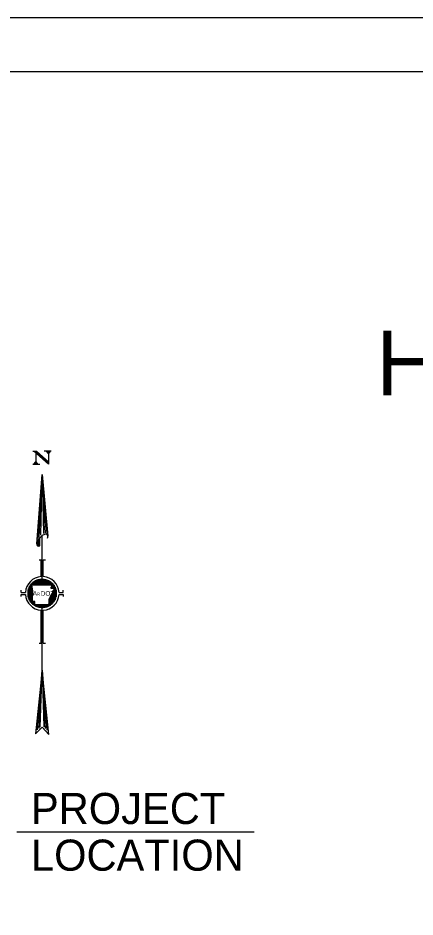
# Model space of a CAD drawing. Extents: x -0.3 to 2.65, y 0 to 1.9.
# Drawn here: x 0.3593 to 0.5124, y 0.5699 to 0.9167 of the extents above; entities that cross this region are included whole.
import ezdxf

# ---------------------------------------------------------------- set-up
doc = ezdxf.new("R2010")
doc.units = 0
for name, color, linetype in [('Default', 7, 'Continuous'), ('SHET_Annotations', 7, 'Continuous'), ('SHET_Border-Lines', 7, 'Continuous'), ('SHET_Border-Text', 7, 'Continuous')]:
    doc.layers.add(name, color=color, linetype=linetype)

msp = doc.modelspace()

# ---------------------------------------------------------------- linework, layer by layer
at = {"layer": 'Default'}
msp.add_line((0.3588331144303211, 0.6027512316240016), (0.4503996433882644, 0.6027512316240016), dxfattribs=at)
at = {"layer": 'SHET_Border-Lines'}
for points in [[(0, 0), (1.416666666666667, 0), (1.416666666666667, 0.9166666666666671), (0, 0.9166666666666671)], [(0.02083333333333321, 0.02083333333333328), (1.3958333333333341, 0.02083333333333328), (1.3958333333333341, 0.8958333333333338), (0.02083333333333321, 0.8958333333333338)]]:
    msp.add_lwpolyline(points, close=True, dxfattribs=at)
at = {"layer": 'SHET_Border-Text'}
for p, q in [((0.36499485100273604, 0.7495318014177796), (0.36647240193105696, 0.7495318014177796)), ((0.3654447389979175, 0.7495318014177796), (0.37101124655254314, 0.7445858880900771)), ((0.3655086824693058, 0.7495318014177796), (0.37101124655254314, 0.7446504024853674)), ((0.365573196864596, 0.7495318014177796), (0.37101124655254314, 0.7446932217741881)), ((0.3656371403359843, 0.7495318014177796), (0.37101124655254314, 0.7447571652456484)), ((0.36570165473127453, 0.7495318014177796), (0.37101124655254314, 0.7447999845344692)), ((0.3657655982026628, 0.7495318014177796), (0.37101124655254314, 0.7448644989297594)), ((0.3658084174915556, 0.7495318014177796), (0.37101124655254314, 0.7449073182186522)), ((0.36587293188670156, 0.7495318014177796), (0.37101124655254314, 0.7449712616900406)), ((0.3659368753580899, 0.7495318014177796), (0.37101124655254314, 0.7450140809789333)), ((0.36600138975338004, 0.7495318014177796), (0.37101124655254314, 0.7450785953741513)), ((0.36606533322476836, 0.7495318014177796), (0.37101124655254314, 0.7451425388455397)), ((0.36612984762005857, 0.7495318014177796), (0.37101124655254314, 0.7451853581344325)), ((0.366150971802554, 0.7495318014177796), (0.366150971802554, 0.7445858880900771)), ((0.36619379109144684, 0.7495318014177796), (0.37101124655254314, 0.7452498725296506)), ((0.3662366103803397, 0.7495318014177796), (0.37101124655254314, 0.7452926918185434)), ((0.3663011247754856, 0.7495318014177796), (0.37101124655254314, 0.7453566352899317)), ((0.3663650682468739, 0.7495318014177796), (0.37101124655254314, 0.7453994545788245)), ((0.36642958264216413, 0.7495318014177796), (0.37101124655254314, 0.7454639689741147)), ((0.36647240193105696, 0.7495318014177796), (0.37101124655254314, 0.7454850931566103)), ((0.3706898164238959, 0.7495318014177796), (0.3694480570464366, 0.7495318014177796)), ((0.3721456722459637, 0.7495318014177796), (0.3706898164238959, 0.7495318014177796)), ((0.37101124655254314, 0.7495318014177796), (0.37101124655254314, 0.7445858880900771)), ((0.36499485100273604, 0.7445858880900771), (0.36647240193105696, 0.7445858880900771)), ((0.36647240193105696, 0.7445858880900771), (0.36771416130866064, 0.7445858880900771)), ((0.3669862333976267, 0.713070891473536), (0.3669862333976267, 0.7146123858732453)), ((0.36728596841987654, 0.7130069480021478), (0.36728596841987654, 0.7150622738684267)), ((0.36767134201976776, 0.7130069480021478), (0.36767134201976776, 0.716025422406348)), ((0.36865618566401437, 0.7003752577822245), (0.36865618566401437, 0.7169891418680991)), ((0.36666480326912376, 0.7133278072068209), (0.36666480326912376, 0.7139700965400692)), ((0.3674355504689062, 0.7076328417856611), (0.3682491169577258, 0.7076328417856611)), ((0.3682491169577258, 0.7011671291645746), (0.3682491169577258, 0.7076328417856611)), ((0.36906268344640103, 0.701188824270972), (0.36906268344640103, 0.7076328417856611)), ((0.36906268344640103, 0.7076328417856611), (0.3698762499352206, 0.7076328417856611)), ((0.3635818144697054, 0.6922607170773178), (0.3635818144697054, 0.6971209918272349)), ((0.36377478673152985, 0.6919181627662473), (0.36377478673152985, 0.6974846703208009)), ((0.363988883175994, 0.6915973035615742), (0.363988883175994, 0.6978061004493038)), ((0.3641812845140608, 0.6912975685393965), (0.3641812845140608, 0.6981269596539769)), ((0.36439538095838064, 0.6911045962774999), (0.36439538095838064, 0.6983838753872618)), ((0.3645883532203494, 0.6908693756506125), (0.3645883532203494, 0.6985768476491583)), ((0.3650376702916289, 0.6955366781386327), (0.3646522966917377, 0.6980201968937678)), ((0.3646522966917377, 0.6980201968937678), (0.372060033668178, 0.6980201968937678)), ((0.3648024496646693, 0.6980201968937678), (0.3648024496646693, 0.6987909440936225)), ((0.36499485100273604, 0.6980201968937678), (0.36499485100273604, 0.6989622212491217)), ((0.3652089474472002, 0.6980201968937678), (0.3652089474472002, 0.6991546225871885)), ((0.3654019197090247, 0.6980201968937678), (0.3654019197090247, 0.6993047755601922)), ((0.3656160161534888, 0.6980201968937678), (0.3656160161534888, 0.6994332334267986)), ((0.3658084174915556, 0.6980201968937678), (0.3658084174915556, 0.6995616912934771)), ((0.36602251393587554, 0.6980201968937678), (0.36602251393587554, 0.6996684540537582)), ((0.3662154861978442, 0.6980201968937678), (0.3662154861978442, 0.6997757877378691)), ((0.36642958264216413, 0.6980201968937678), (0.36642958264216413, 0.6998614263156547)), ((0.36662198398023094, 0.6980201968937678), (0.36662198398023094, 0.6999470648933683)), ((0.36681495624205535, 0.6980201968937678), (0.36681495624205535, 0.700032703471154)), ((0.36702905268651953, 0.6980201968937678), (0.36702905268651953, 0.7000966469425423)), ((0.36722145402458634, 0.6980201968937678), (0.36722145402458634, 0.7001611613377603)), ((0.3674355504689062, 0.6980201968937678), (0.3674355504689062, 0.7002039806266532)), ((0.36762852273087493, 0.6980201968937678), (0.36762852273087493, 0.700246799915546)), ((0.3678426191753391, 0.6980201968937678), (0.3678426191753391, 0.7002679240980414)), ((0.3680350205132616, 0.6980201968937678), (0.3680350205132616, 0.7003107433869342)), ((0.3682491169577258, 0.6980201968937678), (0.3682491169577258, 0.7003324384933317)), ((0.3684420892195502, 0.6980201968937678), (0.3684420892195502, 0.7003535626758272)), ((0.36865618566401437, 0.6980201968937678), (0.36865618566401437, 0.7003752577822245)), ((0.3688485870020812, 0.6980201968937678), (0.3688485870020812, 0.7003324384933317)), ((0.36906268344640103, 0.6980201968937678), (0.36906268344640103, 0.7003324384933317)), ((0.36925565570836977, 0.6980201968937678), (0.36925565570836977, 0.7002896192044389)), ((0.3694697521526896, 0.6980201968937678), (0.3694697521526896, 0.7002679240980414)), ((0.36966215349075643, 0.6980201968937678), (0.36966215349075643, 0.7002251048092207)), ((0.3698762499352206, 0.6980201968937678), (0.3698762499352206, 0.7001822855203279)), ((0.370069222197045, 0.6980201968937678), (0.370069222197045, 0.7001394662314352)), ((0.37026162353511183, 0.6980201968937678), (0.37026162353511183, 0.7000755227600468)), ((0.370475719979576, 0.6980201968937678), (0.370475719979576, 0.7000110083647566)), ((0.3706686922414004, 0.6980201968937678), (0.3706686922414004, 0.6999470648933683)), ((0.3708827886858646, 0.6980201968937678), (0.3708827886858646, 0.6998614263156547)), ((0.3710751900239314, 0.6980201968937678), (0.3710751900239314, 0.6997757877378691)), ((0.3712892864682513, 0.6980201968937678), (0.3712892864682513, 0.6996684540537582)), ((0.37148225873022, 0.6980201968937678), (0.37148225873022, 0.6995616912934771)), ((0.3716963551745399, 0.6980201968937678), (0.3716963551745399, 0.6994332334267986)), ((0.3718887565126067, 0.6980201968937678), (0.3718887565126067, 0.6992830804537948)), ((0.37218849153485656, 0.6973562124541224), (0.3719104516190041, 0.6967784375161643)), ((0.372060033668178, 0.6980201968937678), (0.372060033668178, 0.6980201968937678)), ((0.372060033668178, 0.6980201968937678), (0.37223131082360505, 0.6977204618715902)), ((0.37210285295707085, 0.6979773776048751), (0.37210285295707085, 0.6991546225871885)), ((0.37210285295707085, 0.6967784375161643), (0.37210285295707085, 0.6971421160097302)), ((0.37223131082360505, 0.6977204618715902), (0.37218849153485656, 0.6973562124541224)), ((0.3722958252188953, 0.6967995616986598), (0.3722958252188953, 0.6989622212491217)), ((0.37250992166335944, 0.6967995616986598), (0.37250992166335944, 0.698812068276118)), ((0.37270232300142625, 0.6967995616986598), (0.37270232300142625, 0.6985979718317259)), ((0.37291641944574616, 0.6967784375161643), (0.37291641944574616, 0.6983838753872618)), ((0.37310939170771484, 0.6967784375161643), (0.37310939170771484, 0.6981697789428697)), ((0.37332348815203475, 0.6966282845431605), (0.37332348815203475, 0.6978700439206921)), ((0.3735158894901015, 0.691854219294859), (0.3735158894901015, 0.6975274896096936)), ((0.37370886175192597, 0.6922395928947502), (0.37370886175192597, 0.6971638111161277)), ((0.36054164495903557, 0.6951084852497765), (0.36054164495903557, 0.6959220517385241)), ((0.36054164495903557, 0.6951084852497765), (0.36217468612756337, 0.6951084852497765)), ((0.36054164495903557, 0.693481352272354), (0.36054164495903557, 0.6942949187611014)), ((0.36054164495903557, 0.6942949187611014), (0.3621749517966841, 0.6942949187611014)), ((0.36317531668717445, 0.6933311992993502), (0.36317531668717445, 0.6960288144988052)), ((0.36336771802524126, 0.6926889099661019), (0.36336771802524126, 0.696649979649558)), ((0.3648024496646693, 0.6906552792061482), (0.3648024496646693, 0.6969925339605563)), ((0.36486639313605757, 0.6917897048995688), (0.3650376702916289, 0.6955366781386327)), ((0.36499485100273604, 0.6950867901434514), (0.36499485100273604, 0.695643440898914)), ((0.3720172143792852, 0.6940163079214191), (0.37173917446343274, 0.693438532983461)), ((0.3718887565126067, 0.6900986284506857), (0.3718887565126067, 0.6936954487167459)), ((0.3719104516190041, 0.6967784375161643), (0.37317333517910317, 0.6967784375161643)), ((0.37244540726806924, 0.6946374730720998), (0.3720172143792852, 0.6940163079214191)), ((0.37210285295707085, 0.6902482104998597), (0.37210285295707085, 0.6940808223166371)), ((0.3722958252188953, 0.6904194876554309), (0.3722958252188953, 0.6943805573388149)), ((0.37268119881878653, 0.6953008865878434), (0.37244540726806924, 0.6946374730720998)), ((0.37250992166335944, 0.6905907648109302), (0.37250992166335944, 0.6947870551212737)), ((0.37268119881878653, 0.6953008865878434), (0.3728952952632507, 0.6958364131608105)), ((0.37270232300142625, 0.6908048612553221), (0.37270232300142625, 0.6953225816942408)), ((0.37325897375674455, 0.6962857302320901), (0.3728952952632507, 0.6958364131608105)), ((0.37291641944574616, 0.6910189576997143), (0.37291641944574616, 0.6958364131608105)), ((0.37310939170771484, 0.6912758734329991), (0.37310939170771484, 0.6960933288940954)), ((0.37317333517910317, 0.6967784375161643), (0.3733446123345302, 0.6965643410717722)), ((0.3733446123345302, 0.6965643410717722), (0.37325897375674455, 0.6962857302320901)), ((0.37332348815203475, 0.6915544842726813), (0.37332348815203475, 0.6964141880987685)), ((0.37392295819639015, 0.6927106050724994), (0.37392295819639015, 0.6966927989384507)), ((0.3741153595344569, 0.6933957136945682), (0.3741153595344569, 0.6960505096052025)), ((0.37512469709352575, 0.6942949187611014), (0.37674903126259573, 0.6942949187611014)), ((0.37512496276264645, 0.6951084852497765), (0.37674903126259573, 0.6951084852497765)), ((0.37674903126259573, 0.6951084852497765), (0.37674903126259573, 0.6959220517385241)), ((0.37674903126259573, 0.6942949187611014), (0.37674903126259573, 0.693481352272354)), ((0.3651878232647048, 0.6915973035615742), (0.36486639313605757, 0.6917897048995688)), ((0.36499485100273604, 0.6904840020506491), (0.36499485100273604, 0.6916829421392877)), ((0.3658084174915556, 0.6915973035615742), (0.3651878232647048, 0.6915973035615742)), ((0.3652089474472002, 0.6903127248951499), (0.3652089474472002, 0.6915756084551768)), ((0.3654019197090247, 0.6901414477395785), (0.3654019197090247, 0.6915756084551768)), ((0.3656160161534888, 0.6900341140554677), (0.3656160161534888, 0.6915756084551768)), ((0.3658084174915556, 0.690269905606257), (0.3658084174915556, 0.6915973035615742)), ((0.37098955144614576, 0.690269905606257), (0.3658084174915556, 0.690269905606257)), ((0.3658084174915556, 0.6898845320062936), (0.3658084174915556, 0.6902482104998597)), ((0.36602251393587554, 0.6897771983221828), (0.36602251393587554, 0.690269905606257)), ((0.3662154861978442, 0.6896704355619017), (0.3662154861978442, 0.690269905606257)), ((0.36642958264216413, 0.689584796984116), (0.36642958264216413, 0.690269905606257)), ((0.36662198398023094, 0.6894991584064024), (0.36662198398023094, 0.690269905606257)), ((0.36681495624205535, 0.6894135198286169), (0.36681495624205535, 0.690269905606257)), ((0.36702905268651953, 0.6893490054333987), (0.36702905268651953, 0.690269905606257)), ((0.36722145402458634, 0.6892850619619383), (0.36722145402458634, 0.690269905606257)), ((0.3674355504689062, 0.6892422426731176), (0.3674355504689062, 0.690269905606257)), ((0.36762852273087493, 0.6891777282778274), (0.36762852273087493, 0.690269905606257)), ((0.3678426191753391, 0.6891566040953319), (0.3678426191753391, 0.690269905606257)), ((0.3680350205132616, 0.6891349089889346), (0.3680350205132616, 0.690269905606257)), ((0.3682491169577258, 0.6890920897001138), (0.3682491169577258, 0.690269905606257)), ((0.3684420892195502, 0.6890709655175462), (0.3684420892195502, 0.690269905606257)), ((0.36865618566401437, 0.6890709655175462), (0.36865618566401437, 0.690269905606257)), ((0.3688485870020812, 0.6890709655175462), (0.3688485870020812, 0.690269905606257)), ((0.36906268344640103, 0.6890920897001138), (0.36906268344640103, 0.690269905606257)), ((0.36925565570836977, 0.6891137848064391), (0.36925565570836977, 0.690269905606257)), ((0.3694697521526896, 0.6891349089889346), (0.3694697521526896, 0.690269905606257)), ((0.36966215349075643, 0.6891777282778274), (0.36966215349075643, 0.690269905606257)), ((0.3698762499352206, 0.6892205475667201), (0.3698762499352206, 0.690269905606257)), ((0.370069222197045, 0.6892633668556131), (0.370069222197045, 0.690269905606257)), ((0.37026162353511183, 0.6893278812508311), (0.37026162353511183, 0.690269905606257)), ((0.370475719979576, 0.6893707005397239), (0.370475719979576, 0.690269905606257)), ((0.3706686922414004, 0.6894563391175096), (0.3706686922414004, 0.690269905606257)), ((0.3708827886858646, 0.6895419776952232), (0.3708827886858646, 0.690269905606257)), ((0.37124646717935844, 0.6908048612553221), (0.37098955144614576, 0.690269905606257)), ((0.3710751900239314, 0.6896276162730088), (0.3710751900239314, 0.6903766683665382)), ((0.3712892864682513, 0.6926677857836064), (0.3711608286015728, 0.6916829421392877)), ((0.3711608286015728, 0.6916829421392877), (0.37124646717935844, 0.6908048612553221)), ((0.37173917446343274, 0.693438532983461), (0.3712892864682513, 0.6926677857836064)), ((0.3712892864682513, 0.6897343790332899), (0.3712892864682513, 0.6924965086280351)), ((0.37148225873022, 0.6898417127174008), (0.37148225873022, 0.6929247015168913)), ((0.3716963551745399, 0.6899701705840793), (0.3716963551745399, 0.6932883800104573)), ((0.3682491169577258, 0.675497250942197), (0.3682491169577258, 0.6882357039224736)), ((0.36865618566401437, 0.6651132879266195), (0.36865618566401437, 0.6890281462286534)), ((0.36906268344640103, 0.675497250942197), (0.36906268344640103, 0.6882357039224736)), ((0.3674355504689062, 0.675497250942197), (0.3682491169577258, 0.675497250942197)), ((0.36906268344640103, 0.675497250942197), (0.3698762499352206, 0.675497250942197)), ((0.36865618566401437, 0.6651132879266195), (0.36609929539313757, 0.6405180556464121)), ((0.3711274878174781, 0.6403299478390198), (0.36865618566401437, 0.6651132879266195)), ((0.36609929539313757, 0.6405180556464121), (0.36865618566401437, 0.6430567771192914)), ((0.36865618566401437, 0.6430567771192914), (0.3711274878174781, 0.6403299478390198))]:
    msp.add_line(p, q, dxfattribs=at)
for points in [[(0.3716963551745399, 0.7495318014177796), (0.37101124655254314, 0.7486754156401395), (0.3703472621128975, 0.7495318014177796), (0.37045459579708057, 0.7494889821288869), (0.3716107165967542, 0.7494889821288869), (0.37101124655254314, 0.7487393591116), (0.370475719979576, 0.7494461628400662), (0.3715462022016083, 0.7494672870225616), (0.37101124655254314, 0.7488249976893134), (0.37056135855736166, 0.7494033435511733), (0.3714394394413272, 0.7494244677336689), (0.37101124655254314, 0.7488895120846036), (0.37064699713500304, 0.7493605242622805), (0.37133210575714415, 0.749381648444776), (0.37101124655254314, 0.7489751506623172), (0.37075433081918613, 0.7493177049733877), (0.37124646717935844, 0.7493388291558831), (0.37101124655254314, 0.7490390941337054), (0.3708399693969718, 0.749274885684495), (0.37113970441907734, 0.7492960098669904), (0.37101124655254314, 0.7491036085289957), (0.37092560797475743, 0.7492531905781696), (0.37105406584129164, 0.7492531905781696), (0.37101124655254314, 0.749167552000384), (0.37098955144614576, 0.749232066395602), (0.37101124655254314, 0.749232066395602)], [(0.3654447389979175, 0.7445858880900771), (0.366150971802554, 0.7454422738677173), (0.36679326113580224, 0.7445858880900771), (0.3667076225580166, 0.7446287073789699), (0.3655303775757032, 0.7446287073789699), (0.36612984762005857, 0.7453783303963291), (0.36668649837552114, 0.7446715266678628), (0.3656160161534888, 0.7446504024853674), (0.36612984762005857, 0.7452926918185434), (0.36660085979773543, 0.7447143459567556), (0.36570165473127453, 0.7446932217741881), (0.36612984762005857, 0.7452281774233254), (0.3664935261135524, 0.7447571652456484), (0.36583011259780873, 0.7447360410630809), (0.366150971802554, 0.7451642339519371), (0.3663867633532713, 0.7447999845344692), (0.3659157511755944, 0.7447788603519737), (0.36612984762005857, 0.7450785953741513), (0.3663011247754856, 0.744842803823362), (0.36600138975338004, 0.7448216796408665), (0.36612984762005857, 0.7450140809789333), (0.3662154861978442, 0.7448644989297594), (0.36608702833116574, 0.7448644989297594), (0.36612984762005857, 0.7449501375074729), (0.3661726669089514, 0.7448856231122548), (0.366150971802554, 0.7448856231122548)], [(0.36651522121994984, 0.7138416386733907), (0.36865618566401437, 0.7405180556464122), (0.37079715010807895, 0.7167533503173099)], [(0.36702905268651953, 0.7158758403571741), (0.36865618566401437, 0.7405180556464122), (0.37036895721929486, 0.7178027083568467)], [(0.367478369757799, 0.7164536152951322), (0.36865618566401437, 0.7405180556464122), (0.36979061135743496, 0.717931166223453)], [(0.3681423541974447, 0.7171604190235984), (0.36865618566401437, 0.7405180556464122), (0.36914832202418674, 0.717866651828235)], [(0.3667728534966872, 0.6420461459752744), (0.36865618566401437, 0.6651132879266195), (0.3704545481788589, 0.6419711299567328)], [(0.36988896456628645, 0.6426033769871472), (0.36865618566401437, 0.6651132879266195), (0.3673411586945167, 0.642612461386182)], [(0.36790903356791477, 0.6431576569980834), (0.36865618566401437, 0.6651132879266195), (0.36930227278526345, 0.6432366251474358)]]:
    msp.add_lwpolyline(points, dxfattribs=at)
for start, end in [(93.60728333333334, 176.423906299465), (3.576093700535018, 86.41458888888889), (183.61351343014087, 266.41232777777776), (273.5988916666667, 356.38648656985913)]:
    msp.add_arc((0.3686498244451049, 0.694703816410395), 0.006487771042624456, start, end, dxfattribs=at)
for start_param, end_param in [(2.6816372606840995, 5.778781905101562), (2.29250568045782, 2.6778136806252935), (5.778781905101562, 6.897373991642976)]:
    msp.add_ellipse((0.3686498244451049, 0.715251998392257), major_axis=(-0.0018992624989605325, -0.002109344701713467), ratio=0.4675851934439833, start_param=start_param, end_param=end_param, dxfattribs=at)

# ---------------------------------------------------------------- texts
at = {"layer": 'Default'}
for s, p in [('PROJECT', (0.3643081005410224, 0.6057512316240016)), ('LOCATION', (0.3643081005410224, 0.5877512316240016))]:
    msp.add_text(s, height=0.011999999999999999, dxfattribs=at).set_placement(p)
at = {"layer": 'SHET_Annotations'}
msp.add_text('HWY. 34 STR. & APPRS. ', height=0.024999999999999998, dxfattribs=at).set_placement((0.4973878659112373, 0.7710833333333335))
at = {"layer": 'SHET_Border-Text'}
for s, height, p in [('A  DOT', 0.0018155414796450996, (0.36497206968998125, 0.6937826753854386)), ('R', 0.0012103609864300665, (0.3665815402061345, 0.6937826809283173))]:
    msp.add_text(s, height=height, dxfattribs=at).set_placement(p)

doc.saveas('drawing.dxf')
